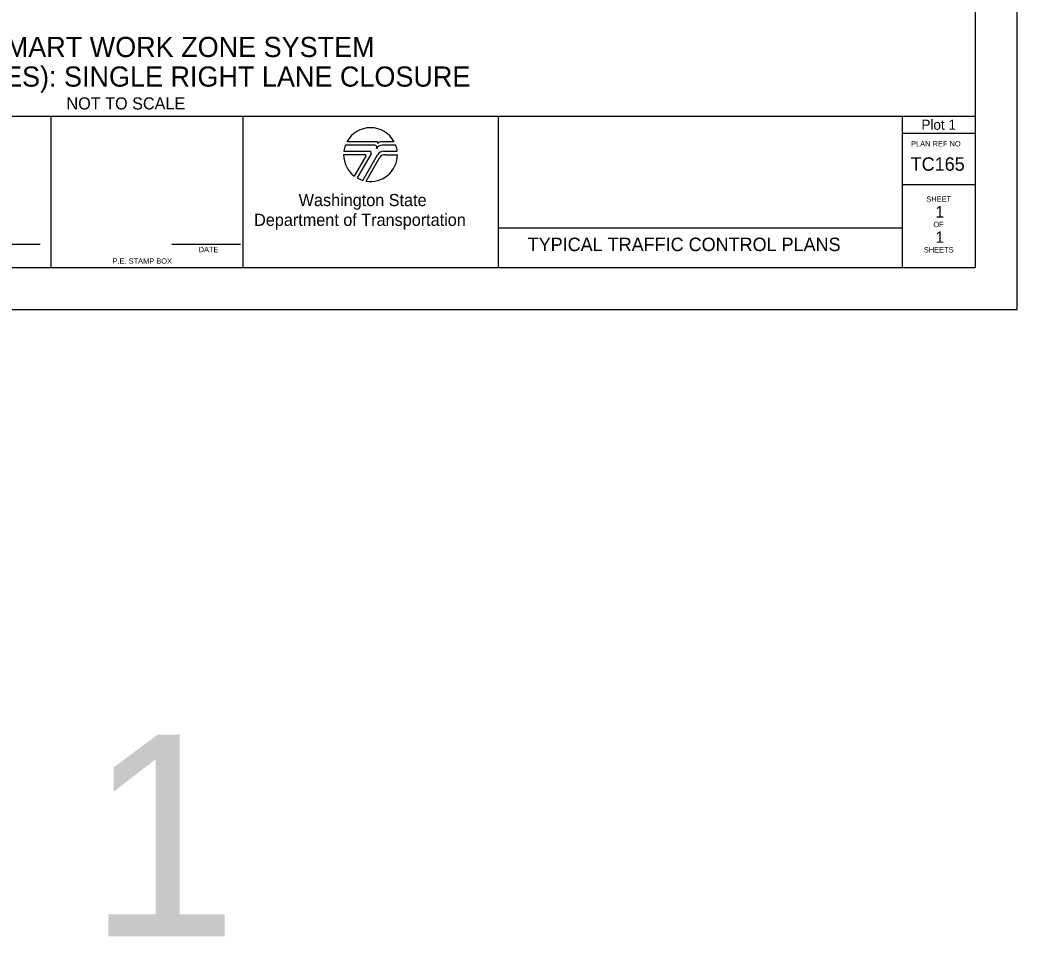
# Model space of a CAD drawing. Extents: x 99999.1 to 100035.7, y 99995 to 100010.7.
# Drawn here: x 100008.65 to 100016.06, y 99995.01 to 100001.84 of the extents above; entities that cross this region are included whole.
import ezdxf

# ---------------------------------------------------------------- set-up
doc = ezdxf.new("R2010")
doc.units = 0
for name, color, linetype in [('SH_DE_DetailHeading1Text', 7, 'Continuous'), ('SH_DE_DetailHeading3Text', 7, 'Continuous'), ('SH_GI_PlotLimits', 7, 'Continuous'), ('SH_GI_SheetBorder', 7, 'Continuous'), ('SH_GI_SheetLocationText', 7, 'Continuous'), ('SH_GI_SheetTextInCells', 7, 'Continuous'), ('SH_GI_TitleBlockText', 7, 'Continuous'), ('SH_GI_WSDOTLogo', 7, 'Continuous')]:
    doc.layers.add(name, color=color, linetype=linetype)

msp = doc.modelspace()

# ---------------------------------------------------------------- linework, layer by layer
at = {"layer": 'SH_GI_PlotLimits'}
msp.add_lwpolyline([(99999.0625, 99999.6875), (100016.0625, 99999.6875), (100016.0625, 100010.6875), (99999.0625, 100010.6875)], close=True, dxfattribs=at)
at = {"layer": 'SH_GI_SheetBorder'}
for p, q in [((100015.75, 100010.375), (100015.75, 100000)), ((100000, 100001.1259), (100015.75, 100001.1259)), ((100008.8828, 100000), (100008.8828, 100001.1259)), ((100010.3089, 100001.1259), (100010.3089, 100000)), ((100012.2055, 100001.1259), (100012.2055, 100000)), ((100015.2079, 100001.1259), (100015.2079, 100000)), ((100015.2079, 100001.0008), (100015.75, 100001.0008)), ((100015.2079, 100000.6176), (100015.75, 100000.6176)), ((100012.2055, 100000.2955), (100015.2079, 100000.2955)), ((100008.2903, 100000.1733), (100008.802, 100000.1733)), ((100009.7797, 100000.1733), (100010.2914, 100000.1733)), ((100000, 100000), (100015.75, 100000))]:
    msp.add_line(p, q, dxfattribs=at)
at = {"layer": 'SH_GI_WSDOTLogo'}
for p, q in [((100011.2894, 100000.9094), (100011.0697, 100000.9094)), ((100011.303, 100000.9354), (100011.0815, 100000.9354)), ((100011.433, 100000.9354), (100011.3351, 100000.9354)), ((100011.343, 100000.9094), (100011.3429, 100000.9094)), ((100011.4448, 100000.9094), (100011.343, 100000.9094)), ((100011.0572, 100000.84), (100011.2148, 100000.84)), ((100011.059, 100000.8661), (100011.2496, 100000.8661)), ((100011.222, 100000.8277), (100011.1364, 100000.6807)), ((100011.261, 100000.8464), (100011.1567, 100000.6672)), ((100011.1989, 100000.6487), (100011.3089, 100000.839)), ((100011.3558, 100000.8661), (100011.4555, 100000.8661)), ((100011.3655, 100000.8394), (100011.4572, 100000.8394)), ((100011.2244, 100000.6428), (100011.3242, 100000.8156))]:
    msp.add_line(p, q, dxfattribs=at)
for centre, radius, start, end in [((100011.2572, 100000.84), 0.2, 28.47865, 151.53204), ((100011.2572, 100000.84), 0.2, 159.69598, 172.50569), ((100011.2894, 100000.8946), 0.0148, 327.8418, 89.99855), ((100011.3429, 100000.861), 0.0484, 89.99529, 147.82376), ((100011.303, 100000.9263), 0.00903, 329.87418, 90.00328), ((100011.3352, 100000.9066), 0.0287, 90.00721, 148.16763), ((100011.2572, 100000.84), 0.2, 7.49431, 20.29406), ((100011.2572, 100000.84), 0.2, 179.99864, 232.84327), ((100011.2149, 100000.8318), 0.0082, 329.74356, 90), ((100011.2572, 100000.84), 0.2, 260.54554, 359.80857), ((100011.2497, 100000.853), 0.0131, 329.76834, 90), ((100011.3558, 100000.8119), 0.0542, 90, 149.99738), ((100011.3654, 100000.7918), 0.0476, 90, 150.05432), ((100011.2572, 100000.84), 0.2, 239.79292, 253.0448)]:
    msp.add_arc(centre, radius, start, end, dxfattribs=at)

# ---------------------------------------------------------------- texts
at = {"layer": 'SH_DE_DetailHeading1Text'}
for s, p in [('6-MILE SMART WORK ZONE SYSTEM', (100007.7097, 100001.5658)), ('FREEWAY (2 LANES): SINGLE RIGHT LANE CLOSURE', (100006.8609, 100001.3458))]:
    msp.add_text(s, height=0.15, dxfattribs=at).set_placement(p)
at = {"layer": 'SH_DE_DetailHeading3Text'}
msp.add_text('NOT TO SCALE', height=0.09, dxfattribs=at).set_placement((100008.9969, 100001.1759))
at = {"layer": 'SH_GI_SheetBorder'}
msp.add_text('PLAN REF NO', height=0.040032, dxfattribs=at).set_placement((100015.2747, 100000.9008))
at = {"layer": 'SH_GI_SheetLocationText'}
for height, p in [(0.075, (100015.3518, 100001.025)), (1.5, (100005.1422, 99995.0267))]:
    msp.add_text('Plot 1', height=height, dxfattribs=at).set_placement(p)
at = {"layer": 'SH_GI_SheetTextInCells'}
for s, height, p in [('Washington State', 0.090072, (100010.7229, 100000.4571)), ('SHEET', 0.04003, (100015.3877, 100000.4896)), ('Department of Transportation', 0.090072, (100010.3916, 100000.3101)), ('OF', 0.04003, (100015.4406, 100000.3008)), ('DATE', 0.04003, (100009.9794, 100000.1141)), ('SHEETS', 0.04003, (100015.3698, 100000.112)), ('P.E. STAMP BOX', 0.040032, (100009.339, 100000.0286))]:
    msp.add_text(s, height=height, dxfattribs=at).set_placement(p)
at = {"layer": 'SH_GI_TitleBlockText'}
for s, height, p in [('TC165', 0.1, (100015.2718, 100000.72)), ('1', 0.085, (100015.4566, 100000.3723)), ('TYPICAL TRAFFIC CONTROL PLANS', 0.1, (100012.4251, 100000.1224)), ('1', 0.085, (100015.4566, 100000.1843))]:
    msp.add_text(s, height=height, dxfattribs=at).set_placement(p)

doc.saveas('drawing.dxf')
